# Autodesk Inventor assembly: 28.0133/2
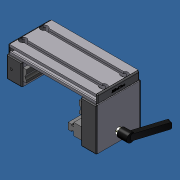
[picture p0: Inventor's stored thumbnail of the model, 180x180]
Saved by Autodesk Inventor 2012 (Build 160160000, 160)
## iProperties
Created: 2007-06
Part Number: 28.0133/2
Document SubType Name: Assembly
Designer: Andy Moles
Description: SLIDE LWG 32X45-90 WITH SIDE CLAMP
Author: Andy Moles
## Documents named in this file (13)
- C:\Andys Backup Data\ANDY'S INVENTOR\INVENTOR LIBRARIES\PARTS LIBRARY\READY FOR USE MODULES LG\28.0133_2 SLIDE LWG 32X45-90 WITH SIDE CLAMP.iam
- C:\Andys Backup Data\ANDY'S INVENTOR\INVENTOR LIBRARIES\PARTS LIBRARY\READY FOR USE MODULES LG\SUBCOMPONENTS\28.0126 SLIDE 45X32.ipt
- C:\Andys Backup Data\ANDY'S INVENTOR\INVENTOR LIBRARIES\PARTS LIBRARY\COMPONENTS LG\22.1094 SLIDE RAIL LG.iam
- C:\Andys Backup Data\ANDY'S INVENTOR\INVENTOR LIBRARIES\PARTS LIBRARY\FASTENING ELEMENTS\SCREWS CAP\21.1200 M8X16.ipt
- C:\Andys Backup Data\ANDY'S INVENTOR\INVENTOR LIBRARIES\PARTS LIBRARY\FASTENING ELEMENTS\NUTS\21.1351 M8 SQUARE NUT.ipt
- C:\Andys Backup Data\ANDY'S INVENTOR\INVENTOR LIBRARIES\PARTS LIBRARY\READY FOR USE MODULES LG\SUBCOMPONENTS\28.9126 SIDE CLAMP 90X32.ipt
- C:\Andys Backup Data\ANDY'S INVENTOR\INVENTOR LIBRARIES\PARTS LIBRARY\READY FOR USE MODULES LG\SUBCOMPONENTS\28.9127 SIDE LOCK SLIDE BAR 23.ipt
- C:\Andys Backup Data\ANDY'S INVENTOR\INVENTOR LIBRARIES\PARTS LIBRARY\COMPONENTS LG\21.1014_1 SLIDE LOCK WITH M6X65 STUD.ipt
- C:\Andys Backup Data\ANDY'S INVENTOR\INVENTOR LIBRARIES\PARTS LIBRARY\FASTENING ELEMENTS\NUTS\21.1330 M6 SQUARE NUT.ipt
- C:\Andys Backup Data\ANDY'S INVENTOR\INVENTOR LIBRARIES\PARTS LIBRARY\END CAPS\22.1061_1 END CAP 90X32 GRAY.ipt
- C:\Andys Backup Data\ANDY'S INVENTOR\INVENTOR LIBRARIES\PARTS LIBRARY\READY FOR USE MODULES LG\SUBCOMPONENTS\28.0225 SLIDE LWG 32X45-90 90X19.ipt
- C:\Andys Backup Data\ANDY'S INVENTOR\INVENTOR LIBRARIES\PARTS LIBRARY\END CAPS\22.1014_1 END CAP 90X19 GRAY.ipt
- C:\Andys Backup Data\ANDY'S INVENTOR\INVENTOR LIBRARIES\PARTS LIBRARY\END CAPS\22.1003_1 END CAP 45x32 Z Gray.iam
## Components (22 placed, 12 different names)
1. 22.1094 SLIDE RAIL LG:1 [sub-assembly] — Mate:28, Mate:29, Flush:29
2. 28.0126 SLIDE 45X32:2 — Mate:3, Flush:4, Mate:6, Mate:19, Flush:27, Mate:27, Mate:32, Flush:34, Flush:35, Mate:33, Flush:36, Flush:37
3. 22.1094 SLIDE RAIL LG:2 [sub-assembly] — Mate:3, Flush:4, Mate:6
4. 28.0225 SLIDE LWG 32X45-90 90X19:1 — Insert:1, Insert:2, Insert:3, Insert:4, Mate:15, Flush:19, Mate:17, Insert:5, Insert:6, Insert:7, Insert:8, Mate:18, Flush:20, Flush:21, Angle:1, Flush:27, Mate:27, Flush:29, Mate:30, Flush:30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
5. 22.1014_1 END CAP 90X19 GRAY:1 — Mate:31, Flush:32, Flush:33
6. 22.1014_1 END CAP 90X19 GRAY:2 — Mate:30, Flush:30, Flush:31
7. 21.1200 M8 x 16:1 — Insert:2
8. 21.1200 M8 x 16:2 — Insert:1
9. 21.1200 M8 x 16:3 — Insert:3
10. 21.1200 M8 x 16:4 — Insert:4
11. 21.1351 M8 SQUARE NUT:1 — Insert:5
12. 21.1351 M8 SQUARE NUT:2 — Insert:6
13. 21.1351 M8 SQUARE NUT:3 — Insert:7
14. 21.1351 M8 SQUARE NUT:4 — Insert:8
15. 28.9126 SIDE CLAMP 90X32:1 — Mate:18, Mate:19, Flush:20, Mate:20, Mate:21, Flush:21, Insert:9, Mate:22, Flush:22, Flush:23, Mate:23, Flush:24, Flush:25, Mate:28, Mate:29
16. 28.9127 SIDE LOCK SLIDE BAR 23:1 — Mate:20, Mate:21, Angle:1, Angle:2, Angle:3, Flush:28
17. 21.1014_1 SLIDE LOCK WITH M6X65 STUD:1 — Insert:9, Angle:2, Mate:26
18. 21.1330 M6 SQUARE NUT:1 — Mate:26, Angle:3, Flush:28
19. 22.1061_1 END CAP 90X32 GRAY:1 — Mate:23, Flush:24, Flush:25
20. 22.1061_1 END CAP 90X32 GRAY:2 — Mate:22, Flush:22, Flush:23
21. 22.1003_1 END CAP 45x32 Z Gray:1 [sub-assembly] — Mate:32, Flush:34, Flush:35
22. 22.1003_1 END CAP 45x32 Z Gray:2 [sub-assembly] — Mate:33, Flush:36, Flush:37
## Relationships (49: Flush 19, Mate 18, Insert 9, Angle 3)
- Mate:3: 28.0126 SLIDE 45X32:2 ↔ 22.1094 SLIDE RAIL LG:2
- Flush:4: 28.0126 SLIDE 45X32:2 ↔ 22.1094 SLIDE RAIL LG:2
- Mate:6: 28.0126 SLIDE 45X32:2 ↔ 22.1094 SLIDE RAIL LG:2
- Insert:1: 28.0225 SLIDE LWG 32X45-90 90X19:1 ↔ 21.1200 M8 x 16:2
- Insert:2: 28.0225 SLIDE LWG 32X45-90 90X19:1 ↔ 21.1200 M8 x 16:1
- Insert:3: 28.0225 SLIDE LWG 32X45-90 90X19:1 ↔ 21.1200 M8 x 16:3
- Insert:4: 28.0225 SLIDE LWG 32X45-90 90X19:1 ↔ 21.1200 M8 x 16:4
- Mate:15: 28.0225 SLIDE LWG 32X45-90 90X19:1
- Flush:19: 28.0225 SLIDE LWG 32X45-90 90X19:1
- Mate:17: 28.0225 SLIDE LWG 32X45-90 90X19:1
- Insert:5: 28.0225 SLIDE LWG 32X45-90 90X19:1 ↔ 21.1351 M8 SQUARE NUT:1
- Insert:6: 28.0225 SLIDE LWG 32X45-90 90X19:1 ↔ 21.1351 M8 SQUARE NUT:2
- Insert:7: 28.0225 SLIDE LWG 32X45-90 90X19:1 ↔ 21.1351 M8 SQUARE NUT:3
- Insert:8: 28.0225 SLIDE LWG 32X45-90 90X19:1 ↔ 21.1351 M8 SQUARE NUT:4
- Mate:18: 28.0225 SLIDE LWG 32X45-90 90X19:1 ↔ 28.9126 SIDE CLAMP 90X32:1
- Mate:19: 28.0126 SLIDE 45X32:2 ↔ 28.9126 SIDE CLAMP 90X32:1
- Flush:20: 28.0225 SLIDE LWG 32X45-90 90X19:1 ↔ 28.9126 SIDE CLAMP 90X32:1
- Mate:20: 28.9126 SIDE CLAMP 90X32:1 ↔ 28.9127 SIDE LOCK SLIDE BAR 23:1
- Mate:21: 28.9126 SIDE CLAMP 90X32:1 ↔ 28.9127 SIDE LOCK SLIDE BAR 23:1
- Flush:21: 28.0225 SLIDE LWG 32X45-90 90X19:1 ↔ 28.9126 SIDE CLAMP 90X32:1
- Angle:1: 28.0225 SLIDE LWG 32X45-90 90X19:1 ↔ 28.9127 SIDE LOCK SLIDE BAR 23:1
- Insert:9: 28.9126 SIDE CLAMP 90X32:1 ↔ 21.1014_1 SLIDE LOCK WITH M6X65 STUD:1
- Angle:2: 28.9127 SIDE LOCK SLIDE BAR 23:1 ↔ 21.1014_1 SLIDE LOCK WITH M6X65 STUD:1
- Mate:22: 28.9126 SIDE CLAMP 90X32:1 ↔ 22.1061_1 END CAP 90X32 GRAY:2
- Flush:22: 28.9126 SIDE CLAMP 90X32:1 ↔ 22.1061_1 END CAP 90X32 GRAY:2
- Flush:23: 28.9126 SIDE CLAMP 90X32:1 ↔ 22.1061_1 END CAP 90X32 GRAY:2
- Mate:23: 28.9126 SIDE CLAMP 90X32:1 ↔ 22.1061_1 END CAP 90X32 GRAY:1
- Flush:24: 28.9126 SIDE CLAMP 90X32:1 ↔ 22.1061_1 END CAP 90X32 GRAY:1
- Flush:25: 28.9126 SIDE CLAMP 90X32:1 ↔ 22.1061_1 END CAP 90X32 GRAY:1
- Flush:27: 28.0126 SLIDE 45X32:2 ↔ 28.0225 SLIDE LWG 32X45-90 90X19:1
- Mate:26: 21.1014_1 SLIDE LOCK WITH M6X65 STUD:1 ↔ 21.1330 M6 SQUARE NUT:1
- Angle:3: 28.9127 SIDE LOCK SLIDE BAR 23:1 ↔ 21.1330 M6 SQUARE NUT:1
- Flush:28: 28.9127 SIDE LOCK SLIDE BAR 23:1 ↔ 21.1330 M6 SQUARE NUT:1
- Mate:27: 28.0126 SLIDE 45X32:2 ↔ 28.0225 SLIDE LWG 32X45-90 90X19:1
- Mate:28: 22.1094 SLIDE RAIL LG:1 ↔ 28.9126 SIDE CLAMP 90X32:1
- Mate:29: 22.1094 SLIDE RAIL LG:1 ↔ 28.9126 SIDE CLAMP 90X32:1
- Flush:29: 22.1094 SLIDE RAIL LG:1 ↔ 28.0225 SLIDE LWG 32X45-90 90X19:1
- Mate:30: 28.0225 SLIDE LWG 32X45-90 90X19:1 ↔ 22.1014_1 END CAP 90X19 GRAY:2
- Flush:30: 28.0225 SLIDE LWG 32X45-90 90X19:1 ↔ 22.1014_1 END CAP 90X19 GRAY:2
- Flush:31: 28.0225 SLIDE LWG 32X45-90 90X19:1 ↔ 22.1014_1 END CAP 90X19 GRAY:2
- Mate:31: 28.0225 SLIDE LWG 32X45-90 90X19:1 ↔ 22.1014_1 END CAP 90X19 GRAY:1
- Flush:32: 28.0225 SLIDE LWG 32X45-90 90X19:1 ↔ 22.1014_1 END CAP 90X19 GRAY:1
- Flush:33: 28.0225 SLIDE LWG 32X45-90 90X19:1 ↔ 22.1014_1 END CAP 90X19 GRAY:1
- Mate:32: 28.0126 SLIDE 45X32:2 ↔ 22.1003_1 END CAP 45x32 Z Gray:1
- Flush:34: 28.0126 SLIDE 45X32:2 ↔ 22.1003_1 END CAP 45x32 Z Gray:1
- Flush:35: 28.0126 SLIDE 45X32:2 ↔ 22.1003_1 END CAP 45x32 Z Gray:1
- Mate:33: 28.0126 SLIDE 45X32:2 ↔ 22.1003_1 END CAP 45x32 Z Gray:2
- Flush:36: 28.0126 SLIDE 45X32:2 ↔ 22.1003_1 END CAP 45x32 Z Gray:2
- Flush:37: 28.0126 SLIDE 45X32:2 ↔ 22.1003_1 END CAP 45x32 Z Gray:2
